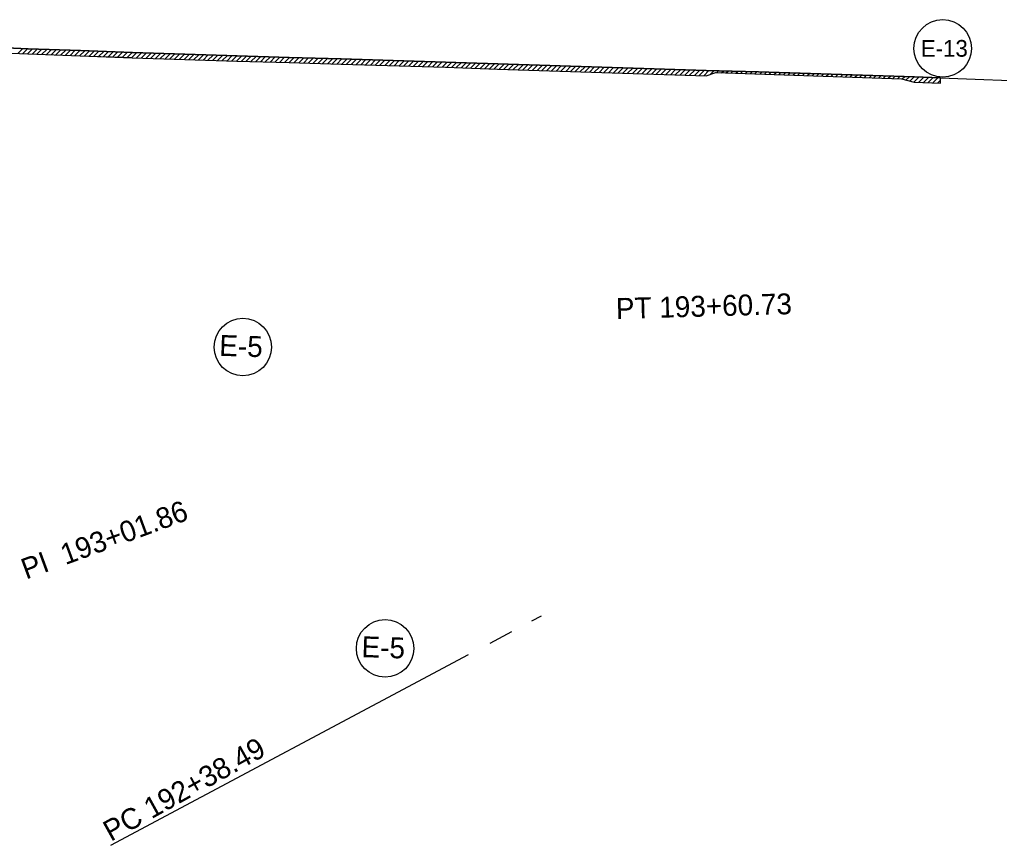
# Model space of a CAD drawing. Extents: x 976877 to 983987, y 1525984 to 1526526.
# Drawn here: x 977564 to 977845.8, y 1526270 to 1526507.4 of the extents above; entities that cross this region are included whole.
import ezdxf

# ---------------------------------------------------------------- set-up
doc = ezdxf.new("R2010")
doc.units = 0
for name, color, linetype in [('R_Erosion', 7, 'Continuous'), ('R_Horz Alg Annot', 7, 'Continuous'), ('R_No Plot', 7, 'Continuous')]:
    doc.layers.add(name, color=color, linetype=linetype)

msp = doc.modelspace()

# ---------------------------------------------------------------- linework, layer by layer
at = {"layer": 'R_Erosion'}
for p, q in [((977563.56, 1526497.61), (977565, 1526499.05)), ((977564.92, 1526497.55), (977566.36, 1526498.99)), ((977566.27, 1526497.49), (977567.72, 1526498.94)), ((977567.64, 1526497.44), (977569.09, 1526498.89)), ((977569.01, 1526497.4), (977570.46, 1526498.85)), ((977570.37, 1526497.35), (977571.83, 1526498.8)), ((977571.74, 1526497.3), (977573.19, 1526498.75)), ((977573.11, 1526497.26), (977574.56, 1526498.71)), ((977574.48, 1526497.21), (977575.93, 1526498.66)), ((977575.84, 1526497.16), (977577.3, 1526498.61)), ((977577.21, 1526497.12), (977578.66, 1526498.57)), ((977578.58, 1526497.07), (977580.03, 1526498.52)), ((977579.95, 1526497.02), (977581.4, 1526498.47)), ((977581.31, 1526496.98), (977582.76, 1526498.42)), ((977582.68, 1526496.93), (977584.13, 1526498.37)), ((977584.04, 1526496.88), (977585.49, 1526498.32)), ((977585.41, 1526496.82), (977586.85, 1526498.27)), ((977586.77, 1526496.77), (977588.22, 1526498.22)), ((977588.13, 1526496.72), (977589.58, 1526498.17)), ((977589.5, 1526496.67), (977590.94, 1526498.12)), ((977590.86, 1526496.62), (977592.31, 1526498.07)), ((977592.22, 1526496.57), (977593.67, 1526498.02)), ((977593.59, 1526496.52), (977595.04, 1526497.97)), ((977594.95, 1526496.47), (977596.4, 1526497.92)), ((977596.32, 1526496.42), (977597.77, 1526497.87)), ((977597.68, 1526496.37), (977599.13, 1526497.82)), ((977599.05, 1526496.32), (977600.5, 1526497.77)), ((977600.41, 1526496.28), (977601.86, 1526497.73)), ((977601.78, 1526496.23), (977603.23, 1526497.68)), ((977603.15, 1526496.18), (977604.6, 1526497.63)), ((977604.51, 1526496.13), (977605.96, 1526497.58)), ((977605.88, 1526496.09), (977607.33, 1526497.54)), ((977607.25, 1526496.04), (977608.7, 1526497.49)), ((977608.61, 1526495.99), (977610.06, 1526497.44)), ((977609.98, 1526495.94), (977611.43, 1526497.39)), ((977611.35, 1526495.9), (977612.8, 1526497.35)), ((977612.72, 1526495.85), (977614.18, 1526497.31)), ((977614.09, 1526495.81), (977615.55, 1526497.27)), ((977615.47, 1526495.77), (977616.92, 1526497.23)), ((977616.84, 1526495.73), (977618.3, 1526497.19)), ((977618.21, 1526495.69), (977619.67, 1526497.15)), ((977619.59, 1526495.65), (977621.05, 1526497.11)), ((977620.96, 1526495.61), (977622.42, 1526497.07)), ((977622.34, 1526495.57), (977623.79, 1526497.03)), ((977623.71, 1526495.53), (977625.17, 1526496.99)), ((977625.08, 1526495.49), (977626.54, 1526496.95)), ((977626.46, 1526495.45), (977627.91, 1526496.91)), ((977627.83, 1526495.41), (977629.29, 1526496.86)), ((977629.2, 1526495.37), (977630.66, 1526496.82)), ((977630.57, 1526495.32), (977632.03, 1526496.78)), ((977631.95, 1526495.28), (977633.4, 1526496.74)), ((977596.45, 1526496.41), (977611.53, 1526495.89)), ((977596.45, 1526496.41), (977611.53, 1526495.89)), ((977633.32, 1526495.24), (977634.77, 1526496.7)), ((977634.69, 1526495.2), (977636.15, 1526496.65)), ((977636.06, 1526495.16), (977637.52, 1526496.61)), ((977637.44, 1526495.11), (977638.89, 1526496.57)), ((977638.81, 1526495.07), (977640.26, 1526496.53)), ((977640.18, 1526495.03), (977641.64, 1526496.49)), ((977641.52, 1526494.99), (977656.52, 1526494.55)), ((977641.52, 1526494.99), (977656.52, 1526494.55)), ((977641.55, 1526494.99), (977643.01, 1526496.45)), ((977642.93, 1526494.95), (977644.38, 1526496.4)), ((977644.3, 1526494.91), (977645.76, 1526496.36)), ((977645.67, 1526494.87), (977647.13, 1526496.32)), ((977647.05, 1526494.83), (977648.5, 1526496.28)), ((977648.42, 1526494.79), (977649.88, 1526496.24)), ((977649.79, 1526494.74), (977651.25, 1526496.2)), ((977651.17, 1526494.7), (977652.63, 1526496.16)), ((977652.54, 1526494.66), (977654, 1526496.12)), ((977653.92, 1526494.62), (977655.37, 1526496.08)), ((977655.29, 1526494.58), (977656.75, 1526496.04)), ((977656.66, 1526494.54), (977658.12, 1526496)), ((977658.04, 1526494.5), (977659.49, 1526495.96)), ((977659.41, 1526494.46), (977660.87, 1526495.92)), ((977660.78, 1526494.42), (977662.24, 1526495.88)), ((977662.16, 1526494.38), (977663.62, 1526495.84)), ((977663.53, 1526494.34), (977664.99, 1526495.8)), ((977664.91, 1526494.3), (977666.36, 1526495.76)), ((977666.28, 1526494.26), (977667.74, 1526495.72)), ((977667.65, 1526494.22), (977669.11, 1526495.68)), ((977669.03, 1526494.18), (977670.48, 1526495.64)), ((977670.4, 1526494.14), (977671.86, 1526495.6)), ((977671.77, 1526494.1), (977673.23, 1526495.56)), ((977673.15, 1526494.06), (977674.61, 1526495.52)), ((977674.52, 1526494.02), (977675.98, 1526495.47)), ((977675.9, 1526493.98), (977677.35, 1526495.43)), ((977677.27, 1526493.94), (977678.73, 1526495.39)), ((977678.64, 1526493.9), (977680.1, 1526495.35)), ((977680.02, 1526493.86), (977681.48, 1526495.31)), ((977681.39, 1526493.82), (977682.85, 1526495.27)), ((977682.77, 1526493.77), (977684.22, 1526495.23)), ((977684.14, 1526493.73), (977685.6, 1526495.19)), ((977685.51, 1526493.69), (977686.97, 1526495.15)), ((977686.88, 1526493.65), (977688.33, 1526495.1)), ((977688.25, 1526493.6), (977689.7, 1526495.05)), ((977689.62, 1526493.55), (977691.07, 1526495)), ((977690.98, 1526493.51), (977692.43, 1526494.96)), ((977692.35, 1526493.46), (977693.8, 1526494.91)), ((977693.71, 1526493.41), (977695.16, 1526494.86)), ((977695.08, 1526493.36), (977696.53, 1526494.81)), ((977696.44, 1526493.31), (977697.89, 1526494.76)), ((977697.81, 1526493.26), (977699.26, 1526494.71)), ((977699.18, 1526493.22), (977700.63, 1526494.66)), ((977700.54, 1526493.17), (977701.99, 1526494.62)), ((977701.91, 1526493.12), (977703.36, 1526494.57)), ((977703.28, 1526493.07), (977704.73, 1526494.52)), ((977704.64, 1526493.03), (977706.1, 1526494.48)), ((977706.01, 1526492.98), (977707.46, 1526494.43)), ((977707.38, 1526492.93), (977708.83, 1526494.39)), ((977708.75, 1526492.89), (977710.2, 1526494.34)), ((977710.12, 1526492.84), (977711.57, 1526494.29)), ((977711.49, 1526492.8), (977712.94, 1526494.25)), ((977712.85, 1526492.75), (977714.31, 1526494.2)), ((977714.22, 1526492.7), (977715.67, 1526494.16)), ((977715.59, 1526492.66), (977717.04, 1526494.11)), ((977716.96, 1526492.61), (977718.41, 1526494.07)), ((977718.33, 1526492.57), (977719.79, 1526494.03)), ((977719.7, 1526492.53), (977721.16, 1526493.98)), ((977721.07, 1526492.48), (977722.53, 1526493.94)), ((977701.47, 1526493.13), (977716.46, 1526492.63)), ((977701.47, 1526493.13), (977716.46, 1526492.63)), ((977722.44, 1526492.44), (977723.9, 1526493.9)), ((977723.82, 1526492.4), (977725.27, 1526493.85)), ((977725.19, 1526492.36), (977726.64, 1526493.81)), ((977726.56, 1526492.31), (977728.01, 1526493.77)), ((977727.93, 1526492.27), (977729.38, 1526493.73)), ((977729.3, 1526492.23), (977730.76, 1526493.68)), ((977730.67, 1526492.18), (977732.13, 1526493.64)), ((977732.04, 1526492.14), (977733.5, 1526493.59)), ((977733.41, 1526492.1), (977734.87, 1526493.55)), ((977734.78, 1526492.05), (977736.24, 1526493.51)), ((977736.15, 1526492.01), (977737.61, 1526493.46)), ((977737.52, 1526491.96), (977738.98, 1526493.42)), ((977738.89, 1526491.92), (977740.35, 1526493.37)), ((977740.26, 1526491.87), (977741.71, 1526493.33)), ((977741.63, 1526491.83), (977743.08, 1526493.28)), ((977743, 1526491.78), (977744.45, 1526493.24)), ((977744.37, 1526491.74), (977745.82, 1526493.19)), ((977745.74, 1526491.7), (977747.19, 1526493.15)), ((977746.45, 1526491.67), (977761.44, 1526491.2)), ((977746.45, 1526491.67), (977761.44, 1526491.2)), ((977747.11, 1526491.65), (977748.57, 1526493.11)), ((977748.48, 1526491.61), (977749.94, 1526493.06)), ((977749.85, 1526491.57), (977751.31, 1526493.02)), ((977751.22, 1526491.52), (977752.68, 1526492.98)), ((977752.6, 1526491.48), (977754.05, 1526492.94)), ((977753.97, 1526491.44), (977755.42, 1526492.89)), ((977755.34, 1526491.39), (977756.79, 1526492.85)), ((977756.71, 1526491.35), (977758.17, 1526492.81)), ((977758.08, 1526491.31), (977759.54, 1526492.76)), ((977759.45, 1526491.27), (977760.91, 1526492.72)), ((977760.82, 1526491.22), (977762.28, 1526492.68)), ((977762.59, 1526491.58), (977763.66, 1526492.65)), ((977764.53, 1526492.11), (977765.04, 1526492.61)), ((977765.9, 1526492.06), (977766.42, 1526492.58)), ((977767.27, 1526492.02), (977767.8, 1526492.54)), ((977768.64, 1526491.97), (977769.18, 1526492.5)), ((977770.01, 1526491.93), (977770.55, 1526492.47)), ((977771.38, 1526491.88), (977771.93, 1526492.43)), ((977772.75, 1526491.84), (977773.31, 1526492.4)), ((977774.12, 1526491.79), (977774.69, 1526492.36)), ((977775.49, 1526491.74), (977776.07, 1526492.32)), ((977806.47, 1526491.38), (977776.49, 1526492.31)), ((977776.86, 1526491.7), (977777.44, 1526492.28)), ((977778.23, 1526491.65), (977778.81, 1526492.24)), ((977779.6, 1526491.61), (977780.18, 1526492.2)), ((977780.96, 1526491.56), (977781.56, 1526492.16)), ((977782.33, 1526491.52), (977782.93, 1526492.11)), ((977783.7, 1526491.47), (977784.3, 1526492.07)), ((977785.07, 1526491.43), (977785.67, 1526492.03)), ((977786.44, 1526491.38), (977787.04, 1526491.98)), ((977787.81, 1526491.34), (977788.41, 1526491.94)), ((977789.18, 1526491.29), (977789.78, 1526491.9)), ((977790.55, 1526491.25), (977791.15, 1526491.86)), ((977791.92, 1526491.2), (977792.53, 1526491.81)), ((977793.29, 1526491.16), (977793.9, 1526491.77)), ((977794.66, 1526491.11), (977795.27, 1526491.73)), ((977796.02, 1526491.07), (977796.64, 1526491.68)), ((977797.39, 1526491.02), (977798.01, 1526491.64)), ((977798.76, 1526490.98), (977799.38, 1526491.6)), ((977800.13, 1526490.93), (977800.75, 1526491.55)), ((977801.5, 1526490.89), (977802.12, 1526491.51)), ((977802.87, 1526490.84), (977803.5, 1526491.47)), ((977804.24, 1526490.8), (977804.87, 1526491.43)), ((977805.61, 1526490.75), (977806.24, 1526491.38)), ((977821.37, 1526490.89), (977806.47, 1526491.38)), ((977806.98, 1526490.71), (977807.61, 1526491.34)), ((977808.35, 1526490.66), (977808.98, 1526491.29)), ((977809.72, 1526490.62), (977810.35, 1526491.25)), ((977811.09, 1526490.57), (977811.72, 1526491.2)), ((977812.45, 1526490.53), (977813.09, 1526491.16)), ((977813.82, 1526490.48), (977814.46, 1526491.11)), ((977815.19, 1526490.44), (977815.83, 1526491.07)), ((977816.56, 1526490.39), (977817.19, 1526491.03)), ((977817.88, 1526490.29), (977818.56, 1526490.98)), ((977819, 1526490), (977819.93, 1526490.94)), ((977820.12, 1526489.71), (977821.3, 1526490.89)), ((977821.22, 1526489.39), (977822.67, 1526490.84)), ((977828.87, 1526490.6), (977821.38, 1526490.89)), ((977822.58, 1526489.34), (977824.03, 1526490.79)), ((977823.94, 1526489.29), (977825.39, 1526490.74)), ((977825.31, 1526489.24), (977826.75, 1526490.68)), ((977826.67, 1526489.19), (977828.11, 1526490.63)), ((977828.03, 1526489.13), (977828.84, 1526489.94)), ((977828.81, 1526489.1), (977828.87, 1526490.6))]:
    msp.add_line(p, q, dxfattribs=at)
for points in [[(977506.49, 1526499.67), (977521.51, 1526499.19), (977536.49, 1526498.66), (977551.48, 1526498.12), (977566.46, 1526497.48)], [(977506.49, 1526499.67), (977521.51, 1526499.19), (977536.49, 1526498.66), (977551.48, 1526498.12), (977566.46, 1526497.48)], [(977581.51, 1526498.47), (977566.52, 1526498.98), (977551.54, 1526499.62)], [(977566.47, 1526497.48), (977581.46, 1526496.97), (977596.45, 1526496.42)], [(977566.47, 1526497.48), (977581.46, 1526496.97), (977596.45, 1526496.41)], [(977626.57, 1526496.95), (977611.58, 1526497.39), (977596.5, 1526497.91), (977581.52, 1526498.47)], [(977686.54, 1526495.16), (977656.56, 1526496.05), (977641.57, 1526496.49), (977626.58, 1526496.95)], [(977611.54, 1526495.89), (977626.53, 1526495.45), (977641.52, 1526494.99)], [(977611.54, 1526495.89), (977626.53, 1526495.45), (977641.52, 1526494.99)], [(977656.52, 1526494.55), (977686.5, 1526493.66), (977701.47, 1526493.13)], [(977656.52, 1526494.55), (977686.5, 1526493.66), (977701.47, 1526493.13)], [(977731.5, 1526493.66), (977716.51, 1526494.13), (977701.52, 1526494.63), (977686.55, 1526495.16)], [(977716.46, 1526492.63), (977731.46, 1526492.16), (977746.45, 1526491.67)], [(977716.46, 1526492.63), (977731.46, 1526492.16), (977746.45, 1526491.67)], [(977776.48, 1526492.31), (977761.49, 1526492.7), (977746.5, 1526493.17), (977731.5, 1526493.66)], [(977761.45, 1526491.2), (977764.23, 1526492.12), (977817.64, 1526490.36), (977821.32, 1526489.39), (977828.81, 1526489.1)], [(977761.45, 1526491.2), (977764.23, 1526492.12), (977817.64, 1526490.36), (977821.32, 1526489.39), (977828.81, 1526489.1)]]:
    msp.add_lwpolyline(points, dxfattribs=at)
for centre in [(977829.49, 1526499.09), (977628.24, 1526413.24), (977669.15, 1526326.64)]:
    msp.add_circle(centre, 8.26, dxfattribs=at)
for centre, start, end in [((977566.52, 1526498.98), 267.5698, 268.0478), ((977566.52, 1526498.98), 267.5698, 268.0478), ((977581.46, 1526496.97), 87.8758, 88.0478), ((977626.53, 1526495.45), 88.2465, 88.3153), ((977596.5, 1526497.91), 267.8758, 268.0018), ((977611.58, 1526497.39), 268.0018, 268.3153), ((977611.58, 1526497.39), 268.0018, 268.3153), ((977641.57, 1526496.49), 268.2465, 268.3114), ((977656.56, 1526496.05), 268.3114, 268.3153), ((977686.5, 1526493.66), 87.9688, 88.3153), ((977701.52, 1526494.63), 267.9688, 268.0706), ((977716.51, 1526494.13), 268.0706, 268.2083), ((977716.51, 1526494.13), 268.0706, 268.2083), ((977731.46, 1526492.16), 88.1395, 88.2083), ((977746.5, 1526493.17), 268.1395, 268.2083), ((977761.49, 1526492.7), 268.2083, 268.514), ((977761.49, 1526492.7), 268.2083, 268.514), ((977776.44, 1526490.81), 88.2082, 88.514), ((977806.42, 1526489.88), 88.1282, 88.2082), ((977821.32, 1526489.39), 87.8108, 88.1282)]:
    msp.add_arc(centre, 1.5, start, end, dxfattribs=at)
at = {"layer": 'R_Horz Alg Annot'}
for points in [[(977713.98, 1526335.89), (977711.22, 1526334.42)], [(977705.47, 1526331.36), (977699.25, 1526328.06)], [(977693.08, 1526324.77), (977590.19, 1526270.02)]]:
    msp.add_lwpolyline(points, dxfattribs=at)
at = {"layer": 'R_No Plot'}
msp.add_lwpolyline([(977551.54, 1526499.62), (977566.52, 1526498.98), (977581.51, 1526498.47), (977596.5, 1526497.91), (977611.58, 1526497.39), (977626.57, 1526496.95), (977641.57, 1526496.49), (977656.56, 1526496.05), (977686.55, 1526495.16), (977701.52, 1526494.63), (977716.51, 1526494.13), (977731.5, 1526493.66), (977746.5, 1526493.17), (977761.49, 1526492.7), (977776.48, 1526492.31), (977806.47, 1526491.38), (977821.37, 1526490.89), (977836.36, 1526490.32), (977851.35, 1526489.72)], dxfattribs=at)
for centre in [(977628.24, 1526413.24), (977628.24, 1526413.24), (977669.15, 1526326.64)]:
    msp.add_circle(centre, 8.26, dxfattribs=at)

# ---------------------------------------------------------------- texts
at = {"layer": 'R_Erosion'}
msp.add_text('E-13', height=4.8, dxfattribs=at).set_placement((977823.16, 1526496.69))
for p in [(977621.39, 1526410.74), (977662.3, 1526324.14)]:
    msp.add_text('E-5 ', height=5.999, rotation=358.0901, dxfattribs=at).set_placement(p)
at = {"layer": 'R_Horz Alg Annot'}
for s, rotation, p in [('PT 193+60.73', 1.5852, (977735.59, 1526421.31)), ('PI  193+01.86', 20.2271, (977565.9, 1526346.39)), ('PC 192+38.49', 29.1324, (977590.28, 1526271.01))]:
    msp.add_text(s, height=6, rotation=rotation, dxfattribs=at).set_placement(p)

doc.saveas('drawing.dxf')
